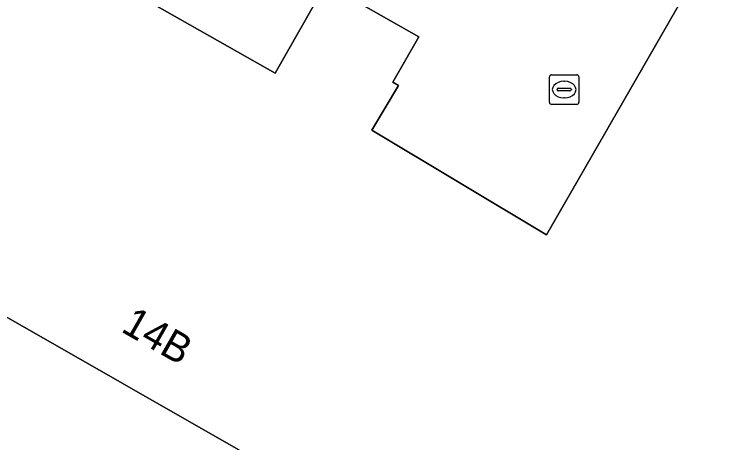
# Model space of a CAD drawing. Extents: x 157132 to 159279, y 384991 to 386650.
# Drawn here: x 158038.68 to 158062.42, y 385625.42 to 385639.93 of the extents above; entities that cross this region are included whole.
import ezdxf

# ---------------------------------------------------------------- set-up
doc = ezdxf.new("R2010")
doc.units = 0
for name, color, linetype in [('IMGEO_Pand', 7, 'Continuous'), ('IMGEO_Pand_nummerreeks', 7, 'Continuous'), ('IMGEO_Rijbaan_lokaal_open', 7, 'Continuous'), ('IMGEO_Rioolput', 7, 'Continuous')]:
    doc.layers.add(name, color=color, linetype=linetype)

msp = doc.modelspace()

# ---------------------------------------------------------------- linework, layer by layer
at = {"layer": 'IMGEO_Pand'}
for points in [[(158074.555, 385665.753), (158070.524, 385658.695), (158071.436, 385658.174), (158065.306, 385647.448), (158065.853, 385647.135), (158065.298, 385646.166), (158064.752, 385646.48), (158056.69, 385632.455), (158050.783, 385636.002), (158051.689, 385637.511), (158051.499, 385637.625), (158052.372, 385639.153), (158049.232, 385640.946), (158047.515, 385637.926), (158035.359, 385644.823)], [(158030.479, 385634.218), (158062.033, 385616.173)]]:
    msp.add_lwpolyline(points, dxfattribs=at)
at = {"layer": 'IMGEO_Rijbaan_lokaal_open'}
for points in [[(158035.359, 385644.823), (158047.515, 385637.926), (158049.232, 385640.946), (158052.372, 385639.153), (158051.499, 385637.625), (158051.689, 385637.511), (158050.783, 385636.002), (158056.69, 385632.455), (158064.752, 385646.48), (158065.298, 385646.166), (158065.853, 385647.135), (158065.306, 385647.448), (158071.436, 385658.174), (158070.524, 385658.695), (158074.555, 385665.753)], [(158062.033, 385616.173), (158030.479, 385634.218)]]:
    msp.add_lwpolyline(points, dxfattribs=at)
at = {"layer": 'IMGEO_Rioolput'}
for p, q in [((158056.864, 385637.874), (158057.716, 385637.874)), ((158056.789, 385636.948), (158056.789, 385637.8)), ((158057.277, 385637.654), (158057.302, 385637.654)), ((158057.79, 385637.8), (158057.79, 385636.948)), ((158057.048, 385637.368), (158057.048, 385637.38)), ((158057.091, 385637.417), (158057.489, 385637.417)), ((158057.532, 385637.38), (158057.532, 385637.368)), ((158057.486, 385637.331), (158057.088, 385637.331)), ((158057.716, 385636.874), (158056.864, 385636.874)), ((158057.3, 385637.094), (158057.275, 385637.094))]:
    msp.add_line(p, q, dxfattribs=at)
for points in [[(158056.864, 385637.874), (158057.716, 385637.874)], [(158056.789, 385636.948), (158056.789, 385637.8)], [(158057.79, 385637.8), (158057.79, 385636.948)], [(158057.716, 385636.874), (158056.864, 385636.874)]]:
    msp.add_lwpolyline(points, dxfattribs=at)
for centre, radius, start, end in [((158056.866, 385637.798), 0.0765, 91.552, 178.448), ((158056.866, 385637.798), 0.0765, 91.552, 178.448), ((158057.714, 385637.798), 0.0765, 1.552, 88.448), ((158057.714, 385637.798), 0.0765, 1.552, 88.448), ((158057.088, 385637.377), 0.0403, 85.8775, 175.7526), ((158057.085, 385637.367), 0.0366, 178.938, 274.7102), ((158057.489, 385637.374), 0.043, 264.8664, 352.4533), ((158057.493, 385637.379), 0.0386, 1.7309, 96.639), ((158056.866, 385636.95), 0.0765, 181.552, 268.448), ((158056.866, 385636.95), 0.0765, 181.552, 268.448), ((158057.714, 385636.95), 0.0765, 271.552, 358.448), ((158057.714, 385636.95), 0.0765, 271.552, 358.448)]:
    msp.add_arc(centre, radius, start, end, dxfattribs=at)
for centre, major_axis, ratio, start_param, end_param in [((158057.276, 385637.374), (-0.387, 0.002), 0.722429, 4.712389, 7.853982), ((158057.301, 385637.374), (-0.39, 0.002), 0.717154, 1.570796, 4.712389)]:
    msp.add_ellipse(centre, major_axis=major_axis, ratio=ratio, start_param=start_param, end_param=end_param, dxfattribs=at)

# ---------------------------------------------------------------- texts
at = {"layer": 'IMGEO_Pand_nummerreeks'}
msp.add_text('14B', height=1, rotation=330.2348, dxfattribs=at).set_placement((158042.261, 385629.208))

doc.saveas('drawing.dxf')
